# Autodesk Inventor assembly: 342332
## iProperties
Company: Hundt & Weber AG Schaltgeräte
Created: 2006-01
Part Number: 342332
Document SubType Name: Assembly
Designer: I.Baliuc
Manufacturer: Standard
Standards Organization: Custom
Description: Spule
Zweck: für Blasspule
Author: I.Baliuc
Revision Number: 342332
